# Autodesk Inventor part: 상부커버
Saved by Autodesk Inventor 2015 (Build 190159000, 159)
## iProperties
Created: 2025-08
Part Number: 상부커버
Material: 일반
Document SubType Name: Modeling
Designer: user
Density: 1 g/cm^3
Appearance: 기본값
Author: user
Author: jhkim
Creation Date: 2025-08-05
Sending System: Autodesk Inventor 2026
Preprocessor: ST-DEVELOPER v20.1
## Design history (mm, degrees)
node "상부커버1"
node "솔리드1"
node "기준1"
